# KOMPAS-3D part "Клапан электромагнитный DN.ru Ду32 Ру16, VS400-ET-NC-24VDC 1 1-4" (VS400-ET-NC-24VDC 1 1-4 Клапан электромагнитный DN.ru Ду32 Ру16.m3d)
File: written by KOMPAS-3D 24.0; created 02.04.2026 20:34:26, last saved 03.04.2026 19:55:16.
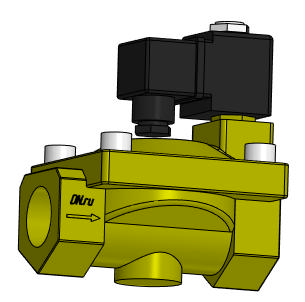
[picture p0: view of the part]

Document properties: Автор: artio; Полное имя файла: C:\Users\artio\OneDrive\Рабочий стол\Клапан электромагнитный DN.ru\VS400-ET-NC\VS400-ET-NC-24VDC 1 1-4 Клапан электромагнитный DN.ru Ду32 Ру16.m3d

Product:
- Body: Тело 1  | qty 1
    Масса: 4.144257
- Part/product: Клапан электромагнитный DN.ru Ду32 Ру16  | designation VS400-ET-NC-24VDC 1 1-4
    Масса: 2.569
    Раздел спецификации: Прочие изделия
    Примечание: D130-04722
    additional columns: ef56311e-7521-43dc-8291-0e6108b3d81d; VS400-ET-NC-220VAC 1 1-4; artio; c; Шероховатость не задана; Да

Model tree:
1. Операция без истории:1

Expressions: VS400-ET-NC-24VDC 1 1-4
